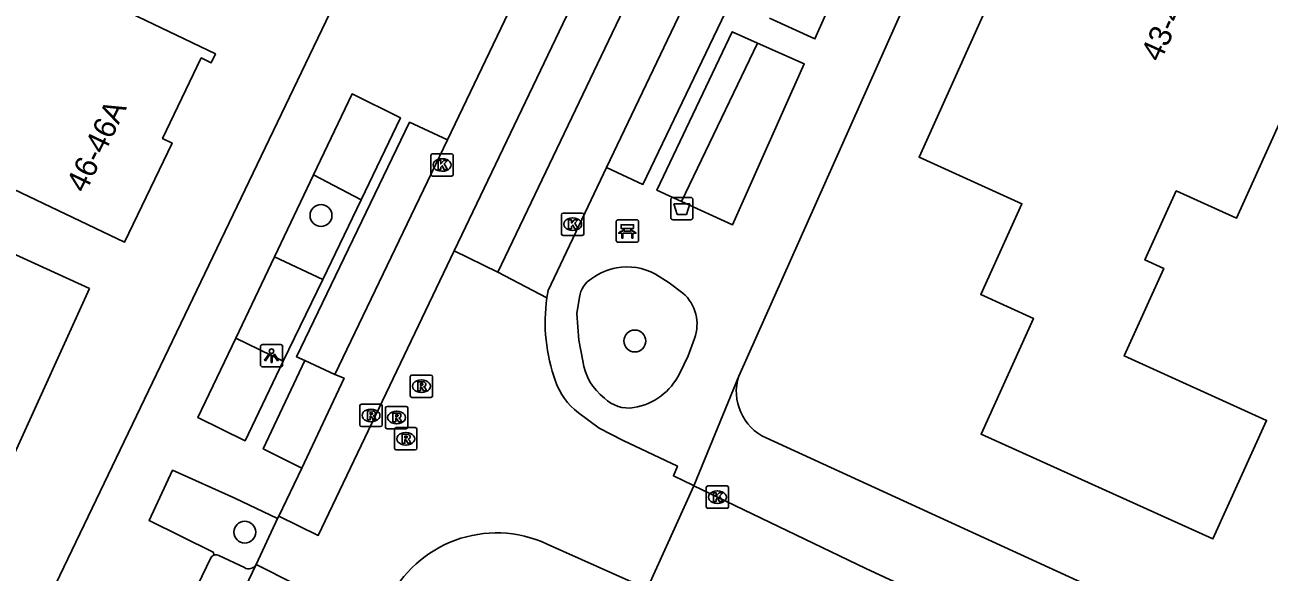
# Model space of a CAD drawing. Extents: x 161355 to 162026, y 386504 to 387459.
# Drawn here: x 161645.5 to 161701.1, y 386965.2 to 386989.7 of the extents above; entities that cross this region are included whole.
import ezdxf

# ---------------------------------------------------------------- set-up
doc = ezdxf.new("R2010")
doc.units = 0
for name, color, linetype in [('IMGEO_Afvalbak', 7, 'Continuous'), ('IMGEO_Bank', 7, 'Continuous'), ('IMGEO_Boom', 7, 'Continuous'), ('IMGEO_Groenvoorziening', 7, 'Continuous'), ('IMGEO_Kolk', 7, 'Continuous'), ('IMGEO_Lichtpunt', 7, 'Continuous'), ('IMGEO_Pand', 7, 'Continuous'), ('IMGEO_Pand_nummerreeks', 7, 'Continuous'), ('IMGEO_Parkeervlak_open', 7, 'Continuous'), ('IMGEO_Rijbaan_lokaal_gesloten', 7, 'Continuous'), ('IMGEO_Rijbaan_lokaal_open', 7, 'Continuous'), ('IMGEO_Rioolput', 7, 'Continuous'), ('IMGEO_Voetpad_open', 7, 'Continuous')]:
    doc.layers.add(name, color=color, linetype=linetype)

msp = doc.modelspace()

# ---------------------------------------------------------------- linework, layer by layer
at = {"layer": 'IMGEO_Afvalbak'}
for p, q in [((161674.379, 386981.082), (161674.379, 386981.882)), ((161674.379, 386981.882), (161674.379, 386981.082)), ((161674.479, 386981.982), (161675.269, 386981.982)), ((161675.269, 386981.982), (161674.479, 386981.982)), ((161675.369, 386981.882), (161675.369, 386981.082)), ((161675.369, 386981.082), (161675.369, 386981.882)), ((161675.269, 386980.982), (161674.479, 386980.982)), ((161674.479, 386980.982), (161675.269, 386980.982))]:
    msp.add_line(p, q, dxfattribs=at)
msp.add_lwpolyline([(161674.522, 386981.696), (161675.226, 386981.696), (161675.077, 386981.226), (161674.671, 386981.226), (161674.522, 386981.696)], dxfattribs=at)
for centre, start, end in [((161674.479, 386981.882), 90, 180), ((161674.479, 386981.882), 90, 180), ((161675.269, 386981.882), 0, 90), ((161675.269, 386981.882), 360, 90), ((161674.479, 386981.082), 180, 270), ((161674.479, 386981.082), 180, 270), ((161675.269, 386981.082), 270, 0), ((161675.269, 386981.082), 270, 0)]:
    msp.add_arc(centre, 0.1, start, end, dxfattribs=at)
at = {"layer": 'IMGEO_Bank'}
for p, q in [((161671.939, 386980.056), (161671.939, 386980.897)), ((161671.939, 386980.897), (161671.939, 386980.056)), ((161672.014, 386980.981), (161672.855, 386980.981)), ((161672.855, 386980.981), (161672.014, 386980.981)), ((161672.248, 386980.487), (161672.248, 386980.593)), ((161672.292, 386980.593), (161672.292, 386980.487)), ((161672.58, 386980.599), (161672.298, 386980.599)), ((161672.586, 386980.487), (161672.586, 386980.593)), ((161672.63, 386980.593), (161672.63, 386980.487)), ((161672.939, 386980.906), (161672.939, 386980.065)), ((161672.939, 386980.065), (161672.939, 386980.906)), ((161672.636, 386980.379), (161672.243, 386980.379)), ((161672.298, 386980.481), (161672.58, 386980.481)), ((161672.864, 386979.981), (161672.023, 386979.981)), ((161672.023, 386979.981), (161672.864, 386979.981))]:
    msp.add_line(p, q, dxfattribs=at)
for points in [[(161672.242, 386980.599), (161672.156, 386980.599), (161672.156, 386980.76), (161672.719, 386980.76), (161672.719, 386980.599), (161672.636, 386980.599)], [(161672.186, 386980.379), (161672.044, 386980.379), (161672.156, 386980.481), (161672.242, 386980.481)], [(161672.236, 386980.372), (161672.236, 386980.165), (161672.193, 386980.165), (161672.193, 386980.372)], [(161672.636, 386980.481), (161672.719, 386980.481), (161672.831, 386980.379), (161672.692, 386980.379)], [(161672.686, 386980.372), (161672.686, 386980.165), (161672.642, 386980.165), (161672.642, 386980.372)]]:
    msp.add_lwpolyline(points, dxfattribs=at)
for centre, radius, start, end in [((161672.017, 386980.903), 0.0779, 92.4484, 184.2845), ((161672.017, 386980.903), 0.0779, 92.4484, 184.2845), ((161672.241, 386980.592), 0.00671, 2.8957, 87.1043), ((161672.298, 386980.592), 0.00671, 92.8957, 177.1043), ((161672.58, 386980.592), 0.00671, 2.8957, 87.1043), ((161672.637, 386980.592), 0.00671, 92.8957, 177.1043), ((161672.861, 386980.903), 0.0779, 2.4484, 94.2845), ((161672.861, 386980.903), 0.0779, 2.4484, 94.2845), ((161672.017, 386980.059), 0.0779, 182.4484, 274.2845), ((161672.017, 386980.059), 0.0779, 182.4484, 274.2845), ((161672.186, 386980.372), 0.00671, 2.8957, 87.1043), ((161672.243, 386980.372), 0.00671, 92.8957, 177.1043), ((161672.241, 386980.488), 0.00671, 272.8957, 357.1043), ((161672.298, 386980.488), 0.00671, 182.8957, 267.1043), ((161672.58, 386980.488), 0.00671, 272.8957, 357.1043), ((161672.637, 386980.488), 0.00671, 182.8957, 267.1043), ((161672.635, 386980.372), 0.00671, 2.8957, 87.1043), ((161672.692, 386980.372), 0.00671, 92.8957, 177.1043), ((161672.861, 386980.059), 0.0779, 272.4484, 4.2845), ((161672.861, 386980.059), 0.0779, 272.4484, 4.2845)]:
    msp.add_arc(centre, radius, start, end, dxfattribs=at)
at = {"layer": 'IMGEO_Boom'}
for centre in [(161658.732, 386981.177), (161672.771, 386975.56), (161655.32, 386967.004)]:
    msp.add_circle(centre, 0.489, dxfattribs=at)
at = {"layer": 'IMGEO_Groenvoorziening'}
for points in [[(161674.862, 386981.801), (161678.258, 386988.893)], [(161658.399, 386983), (161660.524, 386981.884)], [(161658.807, 386978.313), (161656.647, 386979.321)], [(161654.917, 386975.688), (161657.046, 386974.651)]]:
    msp.add_lwpolyline(points, dxfattribs=at)
at = {"layer": 'IMGEO_Kolk'}
for p, q in [((161663.722, 386983.937), (161664.574, 386983.937)), ((161663.647, 386983.011), (161663.647, 386983.863)), ((161664.135, 386983.717), (161664.16, 386983.717)), ((161664.648, 386983.863), (161664.648, 386983.011)), ((161664.574, 386982.937), (161663.722, 386982.937)), ((161664.158, 386983.157), (161664.133, 386983.157)), ((161669.49, 386980.359), (161669.49, 386981.211)), ((161669.565, 386981.285), (161670.417, 386981.285)), ((161670.491, 386981.211), (161670.491, 386980.359)), ((161669.978, 386981.065), (161670.003, 386981.065)), ((161670.417, 386980.285), (161669.565, 386980.285)), ((161670.001, 386980.505), (161669.976, 386980.505)), ((161675.966, 386968.145), (161675.966, 386968.997)), ((161676.041, 386969.071), (161676.893, 386969.071)), ((161676.967, 386968.997), (161676.967, 386968.145)), ((161676.454, 386968.851), (161676.479, 386968.851)), ((161676.893, 386968.071), (161676.041, 386968.071)), ((161676.477, 386968.291), (161676.452, 386968.291))]:
    msp.add_line(p, q, dxfattribs=at)
for points in [[(161663.722, 386983.937), (161664.574, 386983.937)], [(161663.647, 386983.011), (161663.647, 386983.863)], [(161663.968, 386983.637), (161664.091, 386983.637), (161664.091, 386983.486), (161664.221, 386983.637), (161664.385, 386983.637), (161664.239, 386983.486), (161664.392, 386983.237), (161664.24, 386983.237), (161664.155, 386983.401), (161664.091, 386983.334), (161664.091, 386983.237), (161663.968, 386983.237), (161663.968, 386983.637)], [(161664.648, 386983.863), (161664.648, 386983.011)], [(161664.574, 386982.937), (161663.722, 386982.937)], [(161669.49, 386980.359), (161669.49, 386981.211)], [(161669.565, 386981.285), (161670.417, 386981.285)], [(161670.491, 386981.211), (161670.491, 386980.359)], [(161669.811, 386980.985), (161669.934, 386980.985), (161669.934, 386980.834), (161670.064, 386980.985), (161670.228, 386980.985), (161670.082, 386980.834), (161670.235, 386980.585), (161670.083, 386980.585), (161669.998, 386980.749), (161669.934, 386980.682), (161669.934, 386980.585), (161669.811, 386980.585), (161669.811, 386980.985)], [(161670.417, 386980.285), (161669.565, 386980.285)], [(161675.966, 386968.145), (161675.966, 386968.997)], [(161676.041, 386969.071), (161676.893, 386969.071)], [(161676.967, 386968.997), (161676.967, 386968.145)], [(161676.287, 386968.771), (161676.41, 386968.771), (161676.41, 386968.62), (161676.54, 386968.771), (161676.704, 386968.771), (161676.558, 386968.62), (161676.711, 386968.371), (161676.559, 386968.371), (161676.474, 386968.535), (161676.41, 386968.468), (161676.41, 386968.371), (161676.287, 386968.371), (161676.287, 386968.771)], [(161676.893, 386968.071), (161676.041, 386968.071)]]:
    msp.add_lwpolyline(points, dxfattribs=at)
for centre, start, end in [((161663.724, 386983.861), 91.552, 178.448), ((161663.724, 386983.861), 91.552, 178.448), ((161664.572, 386983.861), 1.552, 88.448), ((161664.572, 386983.861), 1.552, 88.448), ((161663.724, 386983.013), 181.552, 268.448), ((161663.724, 386983.013), 181.552, 268.448), ((161664.572, 386983.013), 271.552, 358.448), ((161664.572, 386983.013), 271.552, 358.448), ((161669.567, 386981.209), 91.552, 178.448), ((161669.567, 386981.209), 91.552, 178.448), ((161670.415, 386981.209), 1.552, 88.448), ((161670.415, 386981.209), 1.552, 88.448), ((161669.567, 386980.361), 181.552, 268.448), ((161669.567, 386980.361), 181.552, 268.448), ((161670.415, 386980.361), 271.552, 358.448), ((161670.415, 386980.361), 271.552, 358.448), ((161676.043, 386968.995), 91.552, 178.448), ((161676.043, 386968.995), 91.552, 178.448), ((161676.891, 386968.995), 1.552, 88.448), ((161676.891, 386968.995), 1.552, 88.448), ((161676.043, 386968.147), 181.552, 268.448), ((161676.043, 386968.147), 181.552, 268.448), ((161676.891, 386968.147), 271.552, 358.448), ((161676.891, 386968.147), 271.552, 358.448)]:
    msp.add_arc(centre, 0.0765, start, end, dxfattribs=at)
for centre, major_axis, ratio, start_param, end_param in [((161664.134, 386983.437), (-0.387, 0.002), 0.722429, 4.712389, 7.853982), ((161664.159, 386983.437), (-0.39, 0.002), 0.717154, 1.570796, 4.712389), ((161669.977, 386980.785), (-0.387, 0.002), 0.722429, 4.712389, 7.853982), ((161670.002, 386980.785), (-0.39, 0.002), 0.717154, 1.570796, 4.712389), ((161676.453, 386968.571), (-0.387, 0.002), 0.722429, 4.712389, 7.853982), ((161676.478, 386968.571), (-0.39, 0.002), 0.717154, 1.570796, 4.712389)]:
    msp.add_ellipse(centre, major_axis=major_axis, ratio=ratio, start_param=start_param, end_param=end_param, dxfattribs=at)
at = {"layer": 'IMGEO_Lichtpunt'}
for p, q in [((161656.02, 386975.304), (161656.02, 386974.497)), ((161656.02, 386975.304), (161656.02, 386974.497)), ((161656.922, 386975.399), (161656.114, 386975.399)), ((161656.922, 386975.399), (161656.114, 386975.399)), ((161657.016, 386974.497), (161657.016, 386975.304)), ((161657.016, 386974.497), (161657.016, 386975.304)), ((161656.114, 386974.403), (161656.922, 386974.403)), ((161656.114, 386974.403), (161656.922, 386974.403))]:
    msp.add_line(p, q, dxfattribs=at)
for points in [[(161656.394, 386974.968), (161656.433, 386974.94), (161656.245, 386974.678), (161656.207, 386974.705), (161656.394, 386974.968)], [(161656.496, 386974.92), (161656.543, 386974.92), (161656.543, 386974.598), (161656.496, 386974.598), (161656.496, 386974.92)], [(161656.606, 386974.94), (161656.644, 386974.967), (161656.831, 386974.705), (161656.792, 386974.677), (161656.606, 386974.94)]]:
    msp.add_lwpolyline(points, dxfattribs=at)
msp.add_circle((161656.519, 386975.102), 0.0994, dxfattribs=at)
for centre, start, end in [((161656.114, 386975.304), 90, 180), ((161656.114, 386975.304), 90, 180), ((161656.922, 386975.304), 0, 90), ((161656.922, 386975.304), 0, 90), ((161656.114, 386974.497), 180, 270), ((161656.114, 386974.497), 180, 270), ((161656.922, 386974.497), 270, 0), ((161656.922, 386974.497), 270, 360)]:
    msp.add_arc(centre, 0.0946, start, end, dxfattribs=at)
at = {"layer": 'IMGEO_Pand'}
for points in [[(161639.028, 387030.532), (161638.508, 387014.846), (161634.791, 387006.94), (161635.073, 387006.762), (161631.945, 387000), (161630.209, 386996.251), (161636.023, 386993.468), (161640.299, 386991.421), (161640.365, 386991.559), (161640.742, 386991.379), (161640.319, 386990.494), (161643.964, 386988.749), (161645.705, 386992.384), (161649.5, 386990.567), (161654.01, 386988.408), (161653.819, 386988.01), (161653.371, 386988.225), (161651.645, 386984.62), (161652.067, 386984.418), (161649.94, 386979.976), (161642.34, 386983.614), (161642.038, 386982.983), (161637.356, 386984.735), (161616.468, 386992.553)], [(161702.304, 386986.826), (161699.693, 386981.057), (161696.993, 386982.279), (161695.594, 386979.189), (161696.432, 386978.81), (161694.658, 386974.89), (161701.031, 386972.006), (161698.631, 386966.703), (161688.264, 386971.395), (161690.605, 386976.567), (161688.246, 386977.635), (161690.086, 386981.701), (161685.488, 386983.788), (161689.639, 386993.011), (161694.038, 386991.005), (161695.084, 386993.316), (161694.688, 386994.367), (161695.294, 386995.706), (161694.209, 386996.197)], [(161648.381, 386977.91), (161643.83, 386979.98), (161641.076, 386981.232), (161639.638, 386978.068), (161635.853, 386979.789), (161634.812, 386977.499), (161628.998, 386980.143), (161627.426, 386976.709), (161626.462, 386974.71), (161636.348, 386969.941), (161637.37, 386972.188), (161637.992, 386973.556), (161644.961, 386970.388), (161648.381, 386977.91)]]:
    msp.add_lwpolyline(points, dxfattribs=at)
at = {"layer": 'IMGEO_Parkeervlak_open'}
for points in [[(161659.348, 386974.057), (161658.012, 386974.684)], [(161654.162, 386965.96), (161655.302, 386965.416)]]:
    msp.add_lwpolyline(points, dxfattribs=at)
for centre, radius, start, end in [((161654.031, 386965.73), 0.264, 60.3728, 107.0073), ((161655.497, 386965.736), 0.375, 238.6276, 332.3421)]:
    msp.add_arc(centre, radius, start, end, dxfattribs=at)
at = {"layer": 'IMGEO_Rijbaan_lokaal_gesloten'}
msp.add_lwpolyline([(161653.421, 386960.496), (161655.829, 386965.562)], dxfattribs=at)
at = {"layer": 'IMGEO_Rijbaan_lokaal_open'}
for points in [[(161666.643, 386978.635), (161685.481, 387018.029), (161686.934, 387021.178)], [(161681.574, 387020.458), (161683.75, 387019.375), (161683.561, 387018.983), (161680.977, 387013.629), (161664.695, 386979.587)], [(161671.511, 386983.329), (161686.779, 387015.299)], [(161664.397, 386984.566), (161667.967, 386992.057)], [(161664.397, 386984.566), (161659.348, 386974.057)], [(161671.511, 386983.329), (161668.89, 386977.819)], [(161656.852, 386967.721), (161658.609, 386966.862), (161664.695, 386979.587)], [(161664.695, 386979.587), (161666.643, 386978.635)], [(161666.643, 386978.635), (161668.836, 386977.492)], [(161659.348, 386974.057), (161659.764, 386973.893), (161657.878, 386969.873)], [(161670.245, 386972.344), (161671.176, 386971.663), (161672.256, 386971.1), (161674.68, 386969.96), (161674.495, 386969.525), (161675.367, 386969.105), (161675.409, 386969.085)], [(161656.852, 386967.721), (161657.878, 386969.873)], [(161673.318, 386964.474), (161675.409, 386969.085)], [(161675.409, 386969.085), (161676.467, 386968.571), (161683.099, 386965.38), (161699.061, 386957.966)], [(161655.829, 386965.562), (161656.79, 386967.618)], [(161656.79, 386967.618), (161656.852, 386967.721)], [(161673.318, 386964.474), (161668.856, 386966.469)], [(161655.829, 386965.562), (161657.516, 386964.711)]]:
    msp.add_lwpolyline(points, dxfattribs=at)
for centre, radius, start, end in [((161675.455, 386976.567), 6.683, 169.2022, 172.0437), ((161676.526, 386976.402), 7.767, 171.9348, 199.8576), ((161672.126, 386974.78), 3.078, 199.2723, 232.3205), ((161666.588, 386961.58), 5.39, 65.1178, 154.7943)]:
    msp.add_arc(centre, radius, start, end, dxfattribs=at)
at = {"layer": 'IMGEO_Rioolput'}
for p, q in [((161662.721, 386973.11), (161662.721, 386973.962)), ((161662.796, 386974.036), (161663.648, 386974.036)), ((161663.722, 386973.962), (161663.722, 386973.11)), ((161663.209, 386973.816), (161663.234, 386973.816)), ((161663.648, 386973.036), (161662.796, 386973.036)), ((161663.232, 386973.256), (161663.207, 386973.256)), ((161660.468, 386971.802), (161660.468, 386972.654)), ((161660.543, 386972.728), (161661.395, 386972.728)), ((161660.956, 386972.508), (161660.981, 386972.508)), ((161661.469, 386972.654), (161661.469, 386971.802)), ((161661.613, 386971.709), (161661.613, 386972.561)), ((161661.688, 386972.635), (161662.54, 386972.635)), ((161662.101, 386972.415), (161662.126, 386972.415)), ((161662.614, 386972.561), (161662.614, 386971.709)), ((161661.395, 386971.728), (161660.543, 386971.728)), ((161660.979, 386971.948), (161660.954, 386971.948)), ((161662.124, 386971.855), (161662.099, 386971.855)), ((161662.099, 386971.683), (161662.951, 386971.683)), ((161662.54, 386971.635), (161661.688, 386971.635)), ((161662.024, 386970.757), (161662.024, 386971.609)), ((161662.512, 386971.463), (161662.537, 386971.463)), ((161663.025, 386971.609), (161663.025, 386970.757)), ((161662.951, 386970.683), (161662.099, 386970.683)), ((161662.535, 386970.903), (161662.51, 386970.903))]:
    msp.add_line(p, q, dxfattribs=at)
for points in [[(161662.721, 386973.11), (161662.721, 386973.962)], [(161662.796, 386974.036), (161663.648, 386974.036)], [(161663.722, 386973.962), (161663.722, 386973.11)], [(161663.31, 386973.734), (161663.058, 386973.736), (161663.058, 386973.336)], [(161663.058, 386973.336), (161663.182, 386973.336), (161663.182, 386973.498), (161663.193, 386973.498)], [(161663.236, 386973.655), (161663.182, 386973.655), (161663.182, 386973.574)], [(161663.182, 386973.574), (161663.234, 386973.574)], [(161663.24, 386973.469), (161663.311, 386973.336), (161663.451, 386973.336), (161663.386, 386973.462)], [(161663.648, 386973.036), (161662.796, 386973.036)], [(161660.468, 386971.802), (161660.468, 386972.654)], [(161660.543, 386972.728), (161661.395, 386972.728)], [(161661.057, 386972.426), (161660.805, 386972.428), (161660.805, 386972.028)], [(161660.983, 386972.347), (161660.929, 386972.347), (161660.929, 386972.266)], [(161660.929, 386972.266), (161660.981, 386972.266)], [(161661.469, 386972.654), (161661.469, 386971.802)], [(161661.613, 386971.709), (161661.613, 386972.561)], [(161661.688, 386972.635), (161662.54, 386972.635)], [(161662.202, 386972.333), (161661.95, 386972.335), (161661.95, 386971.935)], [(161662.128, 386972.254), (161662.074, 386972.254), (161662.074, 386972.173)], [(161662.614, 386972.561), (161662.614, 386971.709)], [(161661.395, 386971.728), (161660.543, 386971.728)], [(161660.805, 386972.028), (161660.929, 386972.028), (161660.929, 386972.19), (161660.94, 386972.19)], [(161660.987, 386972.161), (161661.058, 386972.028), (161661.198, 386972.028), (161661.133, 386972.154)], [(161661.95, 386971.935), (161662.074, 386971.935), (161662.074, 386972.097), (161662.085, 386972.097)], [(161662.074, 386972.173), (161662.126, 386972.173)], [(161662.099, 386971.683), (161662.951, 386971.683)], [(161662.132, 386972.068), (161662.203, 386971.935), (161662.343, 386971.935), (161662.278, 386972.061)], [(161662.54, 386971.635), (161661.688, 386971.635)], [(161662.024, 386970.757), (161662.024, 386971.609)], [(161662.613, 386971.381), (161662.361, 386971.383), (161662.361, 386970.983)], [(161662.361, 386970.983), (161662.485, 386970.983), (161662.485, 386971.145), (161662.496, 386971.145)], [(161662.539, 386971.302), (161662.485, 386971.302), (161662.485, 386971.221)], [(161662.485, 386971.221), (161662.537, 386971.221)], [(161662.543, 386971.116), (161662.614, 386970.983), (161662.754, 386970.983), (161662.689, 386971.109)], [(161663.025, 386971.609), (161663.025, 386970.757)], [(161662.951, 386970.683), (161662.099, 386970.683)]]:
    msp.add_lwpolyline(points, dxfattribs=at)
for centre, radius, start, end in [((161662.798, 386973.96), 0.0765, 91.552, 178.448), ((161662.798, 386973.96), 0.0765, 91.552, 178.448), ((161663.646, 386973.96), 0.0765, 1.552, 88.448), ((161663.646, 386973.96), 0.0765, 1.552, 88.448), ((161663.192, 386973.445), 0.0533, 26.0293, 88.6989), ((161663.218, 386973.763), 0.19, 274.7715, 282.9687), ((161663.242, 386973.559), 0.0964, 77.0061, 93.1865), ((161663.256, 386973.616), 0.0378, 276.6634, 79.6772), ((161663.309, 386973.624), 0.109, 350.3612, 89.416), ((161663.307, 386973.624), 0.112, 277.5842, 350.9817), ((161663.291, 386973.409), 0.108, 29.5134, 73.7905), ((161662.798, 386973.112), 0.0765, 181.552, 268.448), ((161662.798, 386973.112), 0.0765, 181.552, 268.448), ((161663.646, 386973.112), 0.0765, 271.552, 358.448), ((161663.646, 386973.112), 0.0765, 271.552, 358.448), ((161660.545, 386972.652), 0.0765, 91.552, 178.448), ((161660.545, 386972.652), 0.0765, 91.552, 178.448), ((161660.965, 386972.455), 0.19, 274.7715, 282.9687), ((161660.989, 386972.251), 0.0964, 77.0061, 93.1865), ((161661.003, 386972.308), 0.0378, 276.6634, 79.6772), ((161661.056, 386972.316), 0.109, 350.3612, 89.416), ((161661.054, 386972.316), 0.112, 277.5842, 350.9817), ((161661.393, 386972.652), 0.0765, 1.552, 88.448), ((161661.393, 386972.652), 0.0765, 1.552, 88.448), ((161661.69, 386972.559), 0.0765, 91.552, 178.448), ((161661.69, 386972.559), 0.0765, 91.552, 178.448), ((161662.134, 386972.158), 0.0964, 77.0061, 93.1865), ((161662.148, 386972.215), 0.0378, 276.6634, 79.6772), ((161662.201, 386972.223), 0.109, 350.3612, 89.416), ((161662.538, 386972.559), 0.0765, 1.552, 88.448), ((161662.538, 386972.559), 0.0765, 1.552, 88.448), ((161660.545, 386971.804), 0.0765, 181.552, 268.448), ((161660.545, 386971.804), 0.0765, 181.552, 268.448), ((161660.939, 386972.137), 0.0533, 26.0293, 88.6989), ((161661.038, 386972.101), 0.108, 29.5134, 73.7905), ((161661.393, 386971.804), 0.0765, 271.552, 358.448), ((161661.393, 386971.804), 0.0765, 271.552, 358.448), ((161661.69, 386971.711), 0.0765, 181.552, 268.448), ((161661.69, 386971.711), 0.0765, 181.552, 268.448), ((161662.101, 386971.607), 0.0765, 91.552, 178.448), ((161662.101, 386971.607), 0.0765, 91.552, 178.448), ((161662.084, 386972.044), 0.0533, 26.0293, 88.6989), ((161662.11, 386972.362), 0.19, 274.7715, 282.9687), ((161662.199, 386972.223), 0.112, 277.5842, 350.9817), ((161662.183, 386972.008), 0.108, 29.5134, 73.7905), ((161662.538, 386971.711), 0.0765, 271.552, 358.448), ((161662.538, 386971.711), 0.0765, 271.552, 358.448), ((161662.949, 386971.607), 0.0765, 1.552, 88.448), ((161662.949, 386971.607), 0.0765, 1.552, 88.448), ((161662.495, 386971.092), 0.0533, 26.0293, 88.6989), ((161662.521, 386971.41), 0.19, 274.7715, 282.9687), ((161662.545, 386971.206), 0.0964, 77.0061, 93.1865), ((161662.559, 386971.263), 0.0378, 276.6634, 79.6772), ((161662.612, 386971.271), 0.109, 350.3612, 89.416), ((161662.61, 386971.271), 0.112, 277.5842, 350.9817), ((161662.594, 386971.056), 0.108, 29.5134, 73.7905), ((161662.101, 386970.759), 0.0765, 181.552, 268.448), ((161662.101, 386970.759), 0.0765, 181.552, 268.448), ((161662.949, 386970.759), 0.0765, 271.552, 358.448), ((161662.949, 386970.759), 0.0765, 271.552, 358.448)]:
    msp.add_arc(centre, radius, start, end, dxfattribs=at)
for centre, major_axis, ratio, start_param, end_param in [((161663.208, 386973.536), (-0.387, 0.002), 0.722429, 4.712389, 7.853982), ((161663.233, 386973.536), (-0.39, 0.002), 0.717154, 1.570796, 4.712389), ((161660.955, 386972.228), (-0.387, 0.002), 0.722429, 4.712389, 7.853982), ((161660.98, 386972.228), (-0.39, 0.002), 0.717154, 1.570796, 4.712389), ((161662.1, 386972.135), (-0.387, 0.002), 0.722429, 4.712389, 7.853982), ((161662.125, 386972.135), (-0.39, 0.002), 0.717154, 1.570796, 4.712389), ((161662.511, 386971.183), (-0.387, 0.002), 0.722429, 4.712389, 7.853982), ((161662.536, 386971.183), (-0.39, 0.002), 0.717154, 1.570796, 4.712389)]:
    msp.add_ellipse(centre, major_axis=major_axis, ratio=ratio, start_param=start_param, end_param=end_param, dxfattribs=at)
at = {"layer": 'IMGEO_Voetpad_open'}
for points in [[(161677.419, 386973.992), (161689.028, 387000), (161692.864, 387007.756), (161695.643, 387012.888), (161703.036, 387025.535), (161713.413, 387041.445), (161718.884, 387049.626), (161718.954, 387049.732), (161722.833, 387055.531), (161723.819, 387057.006), (161727.598, 387062.069), (161735.832, 387073.978), (161748.817, 387090.782)], [(161675.489, 387024.329), (161663.81, 387000), (161647.042, 386965.072), (161646.394, 386963.7)], [(161686.779, 387015.299), (161688.427, 387014.484), (161673.133, 386982.564), (161671.511, 386983.329)], [(161678.797, 386990.012), (161680.83, 386989.079), (161687.609, 387004.307), (161685.973, 387004.986)], [(161678.258, 386988.893), (161677.127, 386989.4), (161673.763, 386982.308), (161674.862, 386981.801)], [(161674.862, 386981.801), (161677.136, 386980.752), (161680.347, 386987.958), (161678.258, 386988.893)], [(161660.524, 386981.884), (161662.286, 386985.549), (161660.12, 386986.613), (161658.399, 386983)], [(161658.012, 386974.684), (161657.639, 386974.851), (161662.691, 386985.348), (161664.397, 386984.566)], [(161658.399, 386983), (161656.647, 386979.321)], [(161658.807, 386978.313), (161660.524, 386981.884)], [(161656.647, 386979.321), (161654.917, 386975.688)], [(161673.689, 386978.556), (161674.308, 386978.168), (161674.923, 386977.7)], [(161657.046, 386974.651), (161658.807, 386978.313)], [(161670.449, 386974.669), (161670.271, 386975.601), (161670.182, 386976.789), (161670.293, 386977.521)], [(161654.917, 386975.688), (161653.224, 386972.132), (161655.338, 386971.098), (161657.046, 386974.651)], [(161675.437, 386975.672), (161675.156, 386974.901), (161674.768, 386974.097)], [(161657.878, 386969.873), (161656.15, 386970.736), (161658.012, 386974.684)], [(161675.409, 386969.085), (161677.419, 386973.992)], [(161678.646, 386971.221), (161703.934, 386959.616), (161710.18, 386956.726), (161717.11, 386954.446), (161724.516, 386952.463), (161732.347, 386950.52), (161737.556, 386949.582)], [(161653.954, 386965.983), (161653.914, 386966.103), (161651.04, 386967.525), (161652.091, 386969.772), (161654.877, 386968.52), (161656.79, 386967.618)], [(161651.637, 386961.362), (161653.801, 386965.856)]]:
    msp.add_lwpolyline(points, dxfattribs=at)
for centre, radius, start, end in [((161671.487, 386977.335), 1.208, 121.86, 171.1385), ((161672.464, 386976.096), 2.781, 100.7237, 125.4842), ((161672.433, 386976.235), 2.639, 61.5738, 100.6227), ((161673.73, 386976.319), 1.825, 339.2507, 49.1937), ((161672.938, 386974.996), 2.51, 187.4792, 232.6228), ((161672.257, 386975.336), 2.8, 279.7591, 333.7281), ((161679.592, 386973.297), 2.281, 162.2597, 245.5079), ((161672.492, 386974.092), 1.534, 225.3394, 278.9946), ((161654.03, 386965.736), 0.258, 107.0459, 152.3439)]:
    msp.add_arc(centre, radius, start, end, dxfattribs=at)

# ---------------------------------------------------------------- texts
at = {"layer": 'IMGEO_Pand_nummerreeks'}
for s, rotation, p in [('43-45A', 65.6495, (161696.277, 386987.998)), ('46-46A', 64.2277, (161648.185, 386982.136))]:
    msp.add_text(s, height=1, rotation=rotation, dxfattribs=at).set_placement(p)

doc.saveas('drawing.dxf')
